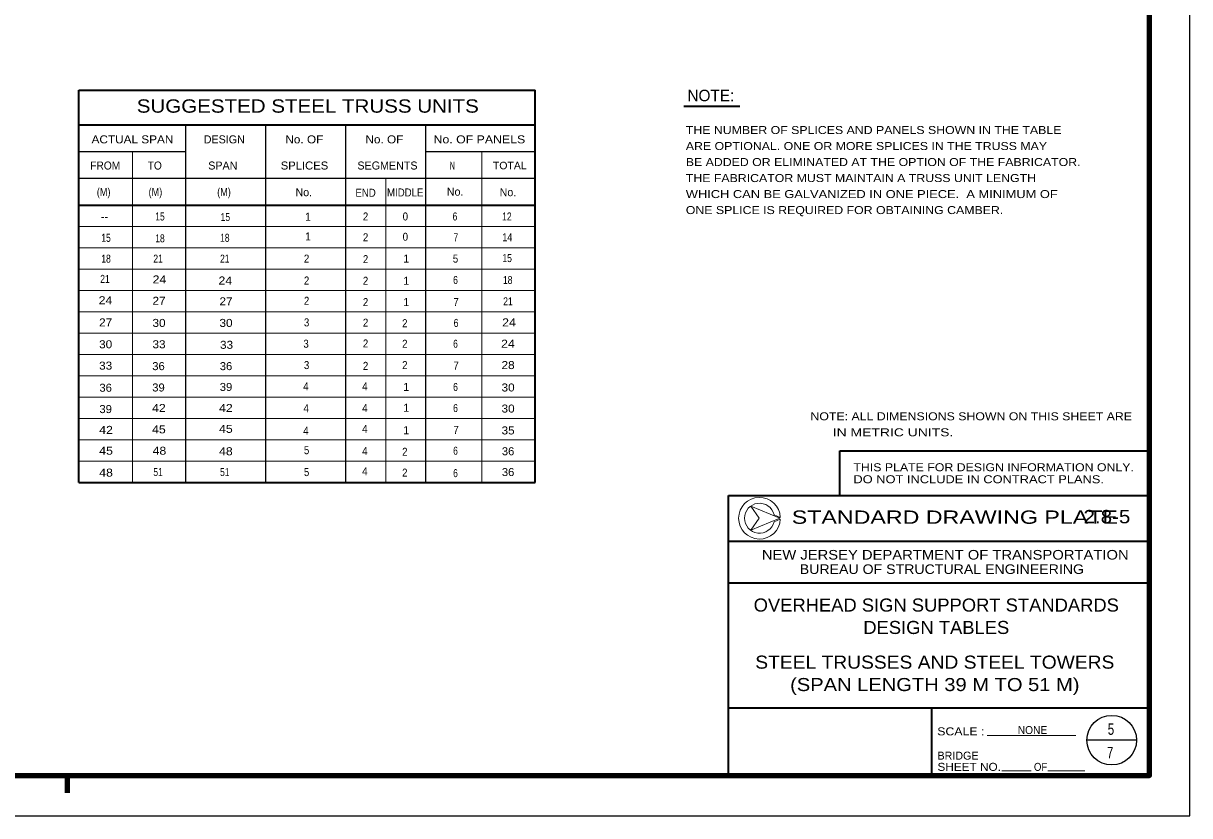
# Model space of a CAD drawing. Extents: x 312601.858 to 312602.699, y 144420.109 to 144420.703.
# Drawn here: x 312602.2619 to 312602.6989, y 144420.1093 to 144420.4063 of the extents above; entities that cross this region are included whole.
import ezdxf
from ezdxf.enums import TextEntityAlignment as Align

# ---------------------------------------------------------------- set-up
doc = ezdxf.new("R2010")
doc.units = 0
doc.header["$LTSCALE"] = 0.0012
for name, color, linetype, lineweight in [('1', 7, 'Continuous', 13), ('2', 7, 'Continuous', 35), ('39', 7, 'Continuous', 35)]:
    doc.layers.add(name, color=color, linetype=linetype, lineweight=lineweight)
doc.layers.add('51', color=7, linetype='Continuous')

msp = doc.modelspace()

# ---------------------------------------------------------------- linework, layer by layer
at = {"layer": '1', "lineweight": 35}
for p, q in [((312602.2827, 144420.2342), (312602.2827, 144420.3812)), ((312602.2827, 144420.3812), (312602.4537, 144420.3812)), ((312602.4537, 144420.2342), (312602.4537, 144420.3812)), ((312602.2827, 144420.3682), (312602.4537, 144420.3682)), ((312602.2827, 144420.3382), (312602.4537, 144420.3382)), ((312602.2827, 144420.2342), (312602.4537, 144420.2342))]:
    msp.add_line(p, q, dxfattribs=at)
at = {"layer": '1', "lineweight": 25}
for p, q in [((312602.3227, 144420.2342), (312602.3227, 144420.3682)), ((312602.3527, 144420.2342), (312602.3527, 144420.3682)), ((312602.3827, 144420.2342), (312602.3827, 144420.3682)), ((312602.4127, 144420.2342), (312602.4127, 144420.3682)), ((312602.2827, 144420.3582), (312602.3227, 144420.3582)), ((312602.4127, 144420.3582), (312602.4537, 144420.3582)), ((312602.2827, 144420.3482), (312602.4537, 144420.3482))]:
    msp.add_line(p, q, dxfattribs=at)
at = {"layer": '1'}
for p, q in [((312602.3027, 144420.2342), (312602.3027, 144420.3582)), ((312602.4336, 144420.2342), (312602.4336, 144420.3582)), ((312602.3977, 144420.2342), (312602.3977, 144420.3482)), ((312602.2827, 144420.3302), (312602.4537, 144420.3302)), ((312602.2827, 144420.3222), (312602.4537, 144420.3222)), ((312602.2827, 144420.3142), (312602.4537, 144420.3142)), ((312602.2827, 144420.3062), (312602.4537, 144420.3062)), ((312602.2827, 144420.2982), (312602.4537, 144420.2982)), ((312602.2827, 144420.2902), (312602.4537, 144420.2902)), ((312602.2827, 144420.2822), (312602.4537, 144420.2822)), ((312602.2827, 144420.2742), (312602.4537, 144420.2742)), ((312602.2827, 144420.2662), (312602.4537, 144420.2662)), ((312602.2827, 144420.2582), (312602.4537, 144420.2582)), ((312602.2827, 144420.2502), (312602.4537, 144420.2502)), ((312602.2827, 144420.2422), (312602.4537, 144420.2422)), ((312602.5432, 144420.2195), (312602.5455, 144420.2205)), ((312602.6285, 144420.1261), (312602.6395, 144420.1261)), ((312602.6458, 144420.1261), (312602.6596, 144420.1261))]:
    msp.add_line(p, q, dxfattribs=at)
for points in [[(312602.5453, 144420.2208), (312602.5344, 144420.2253), (312602.5453, 144420.2208)], [(312602.5455, 144420.2211), (312602.5432, 144420.2221), (312602.5431, 144420.2221)]]:
    msp.add_lwpolyline(points, dxfattribs=at)
for points in [[(312602.5453, 144420.2208), (312602.5344, 144420.2253), (312602.5376, 144420.2208), (312602.5344, 144420.2163)], [(312602.5376, 144420.2208), (312602.5344, 144420.2163), (312602.5453, 144420.2208), (312602.5344, 144420.2253)]]:
    msp.add_lwpolyline(points, close=True, dxfattribs=at)
for radius, start, end in [(0.0078026, 2.21392, 357.78608), (0.0056, 13.69411, 346.30589)]:
    msp.add_arc((312602.5377, 144420.2208), radius, start, end, dxfattribs=at)
at = {"layer": '2'}
msp.add_line((312602.5094, 144420.3752), (312602.5304, 144420.3752), dxfattribs=at)
at = {"layer": '39'}
for p, q in [((312602.5678, 144420.246), (312602.6839, 144420.246)), ((312602.5678, 144420.2293), (312602.5678, 144420.246)), ((312602.5261, 144420.1243), (312602.5261, 144420.2293)), ((312602.5261, 144420.2293), (312602.6839, 144420.2293)), ((312602.6839, 144420.2293), (312602.6839, 144420.1243)), ((312602.5261, 144420.2122), (312602.6839, 144420.2122)), ((312602.5261, 144420.1966), (312602.6839, 144420.1966)), ((312602.5261, 144420.1497), (312602.6839, 144420.1497)), ((312602.6023, 144420.1246), (312602.6023, 144420.1497))]:
    msp.add_line(p, q, dxfattribs=at)
at = {"layer": '39', "lineweight": 13}
for p, q in [((312602.6023, 144420.1497), (312602.6839, 144420.1497)), ((312602.623, 144420.1393), (312602.6562, 144420.1393))]:
    msp.add_line(p, q, dxfattribs=at)
at = {"layer": '39', "lineweight": 25}
for p, q in [((312602.679, 144420.1376), (312602.6604, 144420.1376)), ((312602.4521, 144420.1243), (312602.6839, 144420.1243))]:
    msp.add_line(p, q, dxfattribs=at)
at = {"layer": '39', "lineweight": 158}
msp.add_line((312602.2784, 144420.1179), (312602.2784, 144420.1243), dxfattribs=at)
at = {"layer": '39', "lineweight": 25}
msp.add_lwpolyline([(312601.8579, 144420.1093), (312602.6989, 144420.1093), (312602.6989, 144420.7033)], dxfattribs=at)
at = {"layer": '39', "lineweight": 158}
msp.add_lwpolyline([(312601.9089, 144420.1243), (312602.6839, 144420.1243), (312602.6839, 144420.6643)], dxfattribs=at)
at = {"layer": '39', "lineweight": 13}
msp.add_lwpolyline([(312602.5453, 144420.2208), (312602.5344, 144420.2253), (312602.5376, 144420.2208), (312602.5344, 144420.2163)], close=True, dxfattribs=at)
at = {"layer": '39', "lineweight": 25}
msp.add_circle((312602.6697, 144420.1376), 0.0093005, dxfattribs=at)

# ---------------------------------------------------------------- texts
at = {"layer": '1'}
for s, height, width, p in [('SUGGESTED STEEL TRUSS UNITS', 0.005, 1.15, (312602.36845, 144420.3728)), ('ACTUAL SPAN', 0.003, 1.1, (312602.30275, 144420.3613)), ('No. OF', 0.003, 1.1, (312602.36715, 144420.3613)), ('No. OF', 0.003, 1.1, (312602.39715, 144420.3613)), ('No. OF PANELS', 0.003, 1.15, (312602.43275, 144420.3613)), ('FROM', 0.003, 0.95, (312602.29255, 144420.3515)), ('TO', 0.003, 0.95, (312602.3111, 144420.3515)), ('SPLICES', 0.003, 1.05, (312602.3672, 144420.3515)), ('N', 0.003, 0.7, (312602.4226, 144420.3515)), ('(M)', 0.003, 0.85, (312602.29195, 144420.3416)), ('(M)', 0.003, 0.85, (312602.31135, 144420.3416)), ('(M)', 0.003, 0.85, (312602.33705, 144420.3416)), ('END', 0.003, 0.9, (312602.3901, 144420.3413)), ('MIDDLE', 0.003, 0.9, (312602.40495, 144420.3414)), ('15', 0.003, 0.8, (312602.31305, 144420.3324)), ('15', 0.003, 0.8, (312602.33755, 144420.3322)), ('2', 0.003, 0.9, (312602.3901, 144420.3324)), ('0', 0.003, 0.9, (312602.405, 144420.3324)), ('6', 0.003, 0.8, (312602.4236, 144420.3324)), ('12', 0.003, 0.8, (312602.44305, 144420.3324)), ('15', 0.003, 0.8, (312602.29285, 144420.3244)), ('18', 0.003, 0.8, (312602.31305, 144420.3242)), ('18', 0.003, 0.8, (312602.33735, 144420.3244)), ('2', 0.003, 0.9, (312602.3901, 144420.3246)), ('0', 0.003, 0.9, (312602.405, 144420.3248)), ('7', 0.003, 0.75, (312602.42395, 144420.3246)), ('14', 0.003, 0.85, (312602.4432, 144420.3246)), ('18', 0.003, 0.8, (312602.29285, 144420.3166)), ('21', 0.003, 0.8, (312602.31235, 144420.3166)), ('21', 0.003, 0.8, (312602.33735, 144420.3166)), ('2', 0.003, 0.9, (312602.368, 144420.3166)), ('2', 0.003, 0.9, (312602.3901, 144420.3164)), ('5', 0.003, 0.9, (312602.4238, 144420.3166)), ('15', 0.003, 0.8, (312602.44315, 144420.3168)), ('21', 0.003, 0.8, (312602.29245, 144420.309)), ('24', 0.003, 1.15, (312602.31285, 144420.3088)), ('24', 0.003, 1.15, (312602.33755, 144420.3084)), ('2', 0.003, 0.9, (312602.368, 144420.3084)), ('2', 0.003, 0.9, (312602.3901, 144420.3083)), ('6', 0.003, 0.8, (312602.4238, 144420.3086)), ('18', 0.003, 0.8, (312602.44335, 144420.3086)), ('24', 0.003, 1.15, (312602.29265, 144420.301)), ('27', 0.003, 1.1, (312602.3127, 144420.3008)), ('27', 0.003, 1.1, (312602.3378, 144420.3006)), ('2', 0.003, 0.9, (312602.368, 144420.3008)), ('2', 0.003, 0.9, (312602.3901, 144420.3003)), ('7', 0.003, 0.9, (312602.424, 144420.3003)), ('21', 0.003, 0.8, (312602.44345, 144420.3006)), ('27', 0.003, 1.1, (312602.2927, 144420.2927)), ('30', 0.003, 1.1, (312602.3127, 144420.2925)), ('30', 0.003, 1.1, (312602.3378, 144420.2925)), ('3', 0.003, 0.9, (312602.368, 144420.2927)), ('2', 0.003, 0.9, (312602.3901, 144420.2926)), ('2', 0.003, 0.9, (312602.4048, 144420.2924)), ('6', 0.003, 0.8, (312602.424, 144420.2925)), ('24', 0.003, 1.15, (312602.44385, 144420.2927)), ('30', 0.003, 1.1, (312602.2927, 144420.2845)), ('33', 0.003, 1.1, (312602.3127, 144420.2845)), ('33', 0.003, 1.1, (312602.338, 144420.2843)), ('3', 0.003, 0.9, (312602.3678, 144420.2847)), ('2', 0.003, 0.9, (312602.3901, 144420.2848)), ('2', 0.003, 0.9, (312602.4048, 144420.2847)), ('6', 0.003, 0.8, (312602.4238, 144420.2847)), ('24', 0.003, 1.15, (312602.44345, 144420.2847)), ('33', 0.003, 1.1, (312602.2927, 144420.2765)), ('36', 0.003, 1.05, (312602.3125, 144420.2763)), ('36', 0.003, 1.05, (312602.3378, 144420.2763)), ('3', 0.003, 0.9, (312602.368, 144420.2767)), ('2', 0.003, 0.9, (312602.3901, 144420.2764)), ('2', 0.003, 0.9, (312602.4048, 144420.2767)), ('7', 0.003, 0.9, (312602.424, 144420.2765)), ('28', 0.003, 1.1, (312602.4435, 144420.2767)), ('36', 0.003, 1.05, (312602.2927, 144420.2682)), ('39', 0.003, 1.05, (312602.3125, 144420.2683)), ('39', 0.003, 1.05, (312602.3378, 144420.2685)), ('4', 0.003, 0.95, (312602.36775, 144420.2687)), ('4', 0.003, 0.95, (312602.38985, 144420.2687)), ('6', 0.003, 0.8, (312602.4238, 144420.2685)), ('30', 0.003, 1.1, (312602.4435, 144420.2683)), ('39', 0.003, 1.05, (312602.2927, 144420.2602)), ('42', 0.003, 1.15, (312602.31265, 144420.2606)), ('42', 0.003, 1.15, (312602.33775, 144420.2606)), ('4', 0.003, 0.95, (312602.36785, 144420.2605)), ('4', 0.003, 0.95, (312602.38985, 144420.2606)), ('6', 0.003, 0.8, (312602.4238, 144420.2606)), ('30', 0.003, 1.1, (312602.4435, 144420.2604)), ('42', 0.003, 1.15, (312602.29285, 144420.2524)), ('45', 0.003, 1.15, (312602.31265, 144420.2526)), ('45', 0.003, 1.15, (312602.33775, 144420.2528)), ('4', 0.003, 0.95, (312602.36775, 144420.2521)), ('4', 0.003, 0.95, (312602.38985, 144420.2528)), ('7', 0.003, 0.9, (312602.424, 144420.2524)), ('35', 0.003, 1.1, (312602.4435, 144420.2522)), ('45', 0.003, 1.15, (312602.29285, 144420.2446)), ('48', 0.003, 1.15, (312602.31285, 144420.2446)), ('48', 0.003, 1.15, (312602.33775, 144420.2444)), ('5', 0.003, 0.9, (312602.368, 144420.2448)), ('4', 0.003, 0.95, (312602.38985, 144420.2445)), ('2', 0.003, 0.9, (312602.4048, 144420.2442)), ('6', 0.003, 0.8, (312602.4238, 144420.2446)), ('36', 0.003, 1.05, (312602.4435, 144420.2444)), ('48', 0.003, 1.15, (312602.29285, 144420.2364)), ('51', 0.003, 0.8, (312602.31235, 144420.2366)), ('51', 0.003, 0.8, (312602.33735, 144420.2366)), ('5', 0.003, 0.9, (312602.368, 144420.2366)), ('4', 0.003, 0.95, (312602.38985, 144420.2369)), ('2', 0.003, 0.9, (312602.4048, 144420.2364)), ('6', 0.003, 0.8, (312602.4238, 144420.2362)), ('36', 0.003, 1.05, (312602.4435, 144420.2366)), ('NONE', 0.003, 0.95, (312602.64, 144420.1399))]:
    msp.add_text(s, height=height, dxfattribs=dict(at, width=width)).set_placement(p, align=Align.CENTER)
for s, p in [('DESIGN', (312602.33715, 144420.3613)), ('SPAN', (312602.3366, 144420.3515)), ('SEGMENTS', (312602.3983, 144420.3515)), ('No.', (312602.36695, 144420.3415)), ('No.', (312602.42365, 144420.3417)), ('No.', (312602.44345, 144420.3415)), ('--', (312602.29225, 144420.3324)), ('1', (312602.368525, 144420.3323)), ('1', (312602.368525, 144420.3249)), ('1', (312602.405325, 144420.3166)), ('1', (312602.405325, 144420.3083)), ('1', (312602.405325, 144420.3003)), ('1', (312602.405325, 144420.2685)), ('1', (312602.405325, 144420.2607)), ('1', (312602.405325, 144420.2523))]:
    msp.add_text(s, height=0.003, dxfattribs=at).set_placement(p, align=Align.CENTER)
for s, height, width, p in [('TOTAL', 0.0028, 1.05, (312602.4378, 144420.3516)), ('NOTE: ALL DIMENSIONS SHOWN ON THIS SHEET ARE', 0.003, 1.15, (312602.5568, 144420.2575)), ('     IN METRIC UNITS.', 0.003, 1.3, (312602.5579, 144420.2515))]:
    msp.add_text(s, height=height, dxfattribs=dict(at, width=width)).set_placement(p)
at = {"layer": '2'}
msp.add_text('NOTE:', height=0.0043, dxfattribs=at).set_placement((312602.5107, 144420.3771))
for s, width, p in [('THE NUMBER OF SPLICES AND PANELS SHOWN IN THE TABLE', 1.15, (312602.5101, 144420.3648)), ('ARE OPTIONAL. ONE OR MORE SPLICES IN THE TRUSS MAY', 1.15, (312602.5101, 144420.3588)), ('BE ADDED OR ELIMINATED AT THE OPTION OF THE FABRICATOR.', 1.15, (312602.5101, 144420.3528)), ('THE FABRICATOR MUST MAINTAIN A TRUSS UNIT LENGTH', 1.15, (312602.5101, 144420.3468)), ('WHICH CAN BE GALVANIZED IN ONE PIECE.  A MINIMUM OF', 1.2, (312602.5101, 144420.3408)), ('ONE SPLICE IS REQUIRED FOR OBTAINING CAMBER.', 1.15, (312602.5101, 144420.3348)), ('THIS PLATE FOR DESIGN INFORMATION ONLY.', 1.15, (312602.5729, 144420.2384)), ('DO NOT INCLUDE IN CONTRACT PLANS.', 1.2, (312602.5729, 144420.2339))]:
    msp.add_text(s, height=0.003, dxfattribs=dict(at, width=width)).set_placement(p)
for s, height, width, p in [('2.8-5', 0.005, 1.15, (312602.6679, 144420.2189)), ('OVERHEAD SIGN SUPPORT STANDARDS', 0.0049, 1.05, (312602.60395, 144420.1858)), ('DESIGN TABLES', 0.0049, 1.05, (312602.60395, 144420.1774)), ('STEEL TRUSSES AND STEEL TOWERS', 0.0049, 1.1, (312602.6034, 144420.1644)), ('(SPAN LENGTH 39 M TO 51 M)', 0.0049, 1.15, (312602.6034, 144420.156))]:
    msp.add_text(s, height=height, dxfattribs=dict(at, width=width)).set_placement(p, align=Align.CENTER)
at = {"layer": '39'}
for s, height, width, p in [('STANDARD DRAWING PLATE       ', 0.005, 1.3, (312602.61935, 144420.2187)), ('NEW JERSEY DEPARTMENT OF TRANSPORTATION', 0.003599, 1.15, (312602.6073, 144420.2053)), ('BUREAU OF STRUCTURAL ENGINEERING', 0.0036, 1.1, (312602.60605, 144420.1999)), ('SCALE :', 0.003, 1.15, (312602.61315, 144420.1394)), ('OF', 0.003, 0.9, (312602.64305, 144420.1261))]:
    msp.add_text(s, height=height, dxfattribs=dict(at, width=width)).set_placement(p, align=Align.CENTER)
msp.add_text('BRIDGE', height=0.003, dxfattribs=at).set_placement((312602.6044, 144420.1303))
at = {"layer": '39', "width": 1.1}
msp.add_text('SHEET NO.', height=0.003, dxfattribs=at).set_placement((312602.6044, 144420.1261))
at = {"layer": '51', "width": 0.75}
for s, p in [('5', (312602.6694, 144420.1396)), ('7', (312602.6691, 144420.1308))]:
    msp.add_text(s, height=0.0043, dxfattribs=at).set_placement(p, align=Align.CENTER)

doc.saveas('drawing.dxf')
